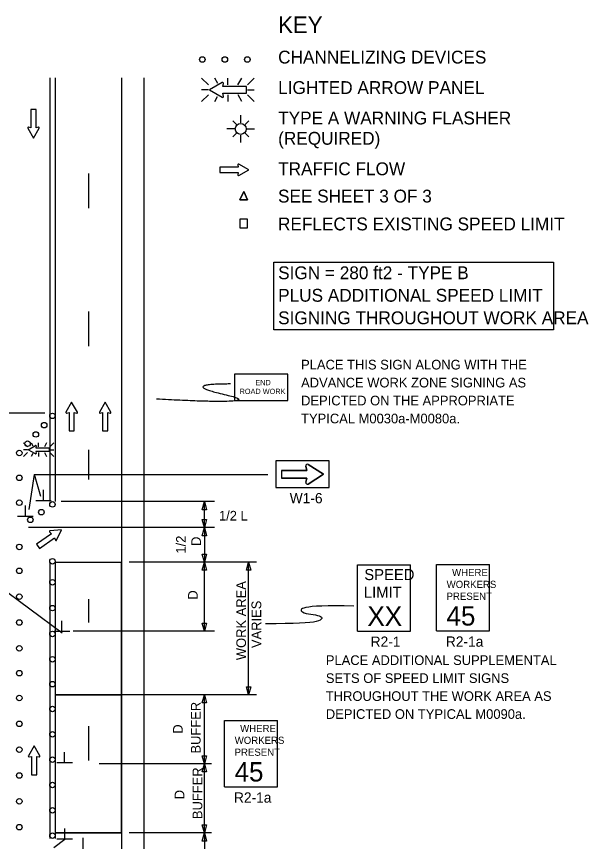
# Model space of a CAD drawing. Extents: x 16473 to 19504, y 4850 to 6923.
# Drawn here: x 17013 to 17427, y 6321 to 6918 of the extents above; entities that cross this region are included whole.
import ezdxf

# ---------------------------------------------------------------- set-up
doc = ezdxf.new("R2010")
doc.units = 0
for name, color, linetype in [('ALI_LEGAL_EX', 7, 'Continuous'), ('MT_SCRATCH_LEVEL_A', 7, 'Continuous'), ('MT_SCRATCH_LEVEL_E', 7, 'Continuous'), ('PAVT_EDGE_EX', 7, 'Continuous'), ('TRAFFIC_SIGNS_PR', 7, 'Continuous'), ('TYPICAL_TEXT_DIMEN_EX', 7, 'Continuous'), ('TYPICAL_TEXT_DIMEN_PR', 7, 'Continuous')]:
    doc.layers.add(name, color=color, linetype=linetype)

msp = doc.modelspace()

# ---------------------------------------------------------------- linework, layer by layer
at = {"layer": 'ALI_LEGAL_EX'}
for points in [[(17065.43, 6804.69), (17065.43, 6779.69)], [(17065.43, 6704.69), (17065.43, 6679.69)], [(17065.43, 6604.69), (17065.43, 6583.06)], [(17065.43, 6496.59), (17065.43, 6479.69)], [(17065.43, 6404.69), (17065.43, 6379.69)]]:
    msp.add_lwpolyline(points, dxfattribs=at)
at = {"layer": 'MT_SCRATCH_LEVEL_A'}
for p, q in [((17041.43, 6437.35), (17041.43, 6327.29)), ((17089.43, 6437.35), (17089.43, 6327.29)), ((17089.43, 6327.29), (17041.43, 6327.29))]:
    msp.add_line(p, q, dxfattribs=at)
for points in [[(17089.39, 6427.29), (17089.39, 6523.11), (17041.43, 6523.11), (17041.43, 6427.29)], [(17041.43, 6327.29), (17089.43, 6327.29), (17089.43, 6427.29), (17041.43, 6427.29)]]:
    msp.add_lwpolyline(points, close=True, dxfattribs=at)
at = {"layer": 'MT_SCRATCH_LEVEL_E'}
for p, q in [((17027.58, 6851.09), (17023.84, 6851.09)), ((17023.84, 6851.09), (17023.84, 6837.83)), ((17027.58, 6851.09), (17023.84, 6851.09)), ((17023.84, 6851.09), (17023.84, 6837.83)), ((17027.58, 6837.83), (17027.58, 6851.09)), ((17027.58, 6837.83), (17027.58, 6851.09)), ((17021.58, 6837.46), (17025.73, 6830.22)), ((17021.58, 6837.46), (17025.73, 6830.22)), ((17023.84, 6837.83), (17022.06, 6838.14)), ((17023.84, 6837.83), (17022.06, 6838.14)), ((17025.73, 6830.22), (17029.84, 6837.46)), ((17025.73, 6830.22), (17029.84, 6837.46)), ((17029.36, 6838.14), (17027.58, 6837.83)), ((17029.36, 6838.14), (17027.58, 6837.83)), ((17173.9, 6809.15), (17160.64, 6809.15)), ((17160.64, 6809.15), (17160.64, 6805.4)), ((17173.9, 6809.15), (17160.64, 6809.15)), ((17160.64, 6809.15), (17160.64, 6805.4)), ((17173.58, 6810.92), (17173.9, 6809.15)), ((17173.58, 6810.92), (17173.9, 6809.15)), ((17181.51, 6807.29), (17174.27, 6811.4)), ((17181.51, 6807.29), (17174.27, 6811.4)), ((17160.64, 6805.4), (17173.9, 6805.4)), ((17160.64, 6805.4), (17173.9, 6805.4)), ((17173.9, 6805.4), (17173.58, 6803.63)), ((17173.9, 6805.4), (17173.58, 6803.63)), ((17174.27, 6803.15), (17181.51, 6807.29)), ((17174.27, 6803.15), (17181.51, 6807.29)), ((17053.33, 6639.17), (17049.22, 6631.93)), ((17053.33, 6639.17), (17049.22, 6631.93)), ((17057.48, 6631.93), (17053.33, 6639.17)), ((17057.48, 6631.93), (17053.33, 6639.17)), ((17077.52, 6639.17), (17073.41, 6631.93)), ((17077.52, 6639.17), (17073.41, 6631.93)), ((17081.67, 6631.93), (17077.52, 6639.17)), ((17081.67, 6631.93), (17077.52, 6639.17)), ((17049.7, 6631.24), (17051.48, 6631.56)), ((17049.7, 6631.24), (17051.48, 6631.56)), ((17051.48, 6631.56), (17051.48, 6618.3)), ((17051.48, 6631.56), (17051.48, 6618.3)), ((17055.22, 6618.3), (17055.22, 6631.56)), ((17055.22, 6631.56), (17057, 6631.24)), ((17055.22, 6618.3), (17055.22, 6631.56)), ((17055.22, 6631.56), (17057, 6631.24)), ((17073.89, 6631.24), (17075.67, 6631.56)), ((17073.89, 6631.24), (17075.67, 6631.56)), ((17075.67, 6631.56), (17075.67, 6618.3)), ((17075.67, 6631.56), (17075.67, 6618.3)), ((17079.41, 6618.3), (17079.41, 6631.56)), ((17079.41, 6631.56), (17081.19, 6631.24)), ((17079.41, 6618.3), (17079.41, 6631.56)), ((17079.41, 6631.56), (17081.19, 6631.24)), ((17051.48, 6618.3), (17055.22, 6618.3)), ((17051.48, 6618.3), (17055.22, 6618.3)), ((17075.67, 6618.3), (17079.41, 6618.3)), ((17075.67, 6618.3), (17079.41, 6618.3)), ((17046, 6546.78), (17037.71, 6546)), ((17046, 6546.78), (17037.71, 6546)), ((17042.44, 6539.23), (17046, 6546.78)), ((17042.44, 6539.23), (17046, 6546.78)), ((17038.7, 6543.94), (17027.83, 6536.35)), ((17038.7, 6543.94), (17027.83, 6536.35)), ((17029.97, 6533.28), (17040.84, 6540.87)), ((17029.97, 6533.28), (17040.84, 6540.87)), ((17037.42, 6545.21), (17038.7, 6543.94)), ((17037.42, 6545.21), (17038.7, 6543.94)), ((17040.84, 6540.87), (17041.6, 6539.23)), ((17040.84, 6540.87), (17041.6, 6539.23)), ((17027.83, 6536.35), (17029.97, 6533.28)), ((17027.83, 6536.35), (17029.97, 6533.28)), ((17026.14, 6390.28), (17022.03, 6383.03)), ((17026.14, 6390.28), (17022.03, 6383.03)), ((17030.28, 6383.03), (17026.14, 6390.28)), ((17030.28, 6383.03), (17026.14, 6390.28)), ((17022.51, 6382.35), (17024.29, 6382.67)), ((17022.51, 6382.35), (17024.29, 6382.67)), ((17024.29, 6382.67), (17024.29, 6369.41)), ((17024.29, 6382.67), (17024.29, 6369.41)), ((17028.03, 6369.41), (17028.03, 6382.67)), ((17028.03, 6382.67), (17029.81, 6382.35)), ((17028.03, 6369.41), (17028.03, 6382.67)), ((17028.03, 6382.67), (17029.81, 6382.35)), ((17024.29, 6369.41), (17028.03, 6369.41)), ((17024.29, 6369.41), (17028.03, 6369.41))]:
    msp.add_line(p, q, dxfattribs=at)
for centre, start, end in [((17021.99, 6837.68), 80.03619, 209.77312), ((17021.99, 6837.68), 80.03619, 209.77312), ((17029.43, 6837.68), 330.42484, 99.96381), ((17029.43, 6837.68), 330.42484, 99.96381), ((17174.04, 6811), 60.42484, 189.96381), ((17174.04, 6811), 60.42484, 189.96381), ((17174.04, 6803.56), 170.03619, 299.77312), ((17174.04, 6803.56), 170.03619, 299.77312), ((17049.63, 6631.7), 150.42484, 279.96381), ((17049.63, 6631.7), 150.42484, 279.96381), ((17057.07, 6631.7), 260.03619, 29.77312), ((17057.07, 6631.7), 260.03619, 29.77312), ((17073.82, 6631.7), 150.42484, 279.96381), ((17073.82, 6631.7), 150.42484, 279.96381), ((17081.26, 6631.7), 260.03619, 29.77312), ((17081.26, 6631.7), 260.03619, 29.77312), ((17037.76, 6545.54), 95.35608, 224.89505), ((17037.76, 6545.54), 95.35608, 224.89505), ((17042.02, 6539.44), 204.96744, 334.70436), ((17042.02, 6539.44), 204.96744, 334.70436), ((17022.43, 6382.81), 150.42484, 279.96381), ((17022.43, 6382.81), 150.42484, 279.96381), ((17029.87, 6382.81), 260.03619, 29.77312), ((17029.87, 6382.81), 260.03619, 29.77312)]:
    msp.add_arc(centre, 0.463, start, end, dxfattribs=at)
at = {"layer": 'PAVT_EDGE_EX'}
for p, q in [((17037.43, 6873.99), (17037.43, 6567.11)), ((17041.43, 6873.99), (17041.43, 6567.11)), ((17089.43, 6873.99), (17089.43, 6149.2)), ((17105.43, 6873.99), (17105.43, 6149.2)), ((17037.43, 6523.35), (17037.43, 6323.29)), ((17041.43, 6523.35), (17041.43, 6476.48)), ((17041.43, 6437.35), (17041.43, 6323.29))]:
    msp.add_line(p, q, dxfattribs=at)
at = {"layer": 'TRAFFIC_SIGNS_PR'}
for p, q in [((17147.32, 6873.68), (17152.25, 6868.75)), ((17159.08, 6869.86), (17156.87, 6873.68)), ((17166.4, 6868.75), (17166.4, 6873.68)), ((17173.64, 6868.75), (17176.48, 6873.68)), ((17180.55, 6868.75), (17185.49, 6873.68)), ((17152.25, 6865.19), (17147.32, 6865.19)), ((17180.55, 6865.19), (17185.49, 6865.19)), ((17147.32, 6856.7), (17152.25, 6861.63)), ((17156.83, 6856.7), (17158.94, 6860.36)), ((17166.4, 6861.63), (17166.4, 6856.7)), ((17176.53, 6856.7), (17173.68, 6861.63)), ((17180.55, 6861.63), (17185.49, 6856.7)), ((17175.66, 6841.4), (17175.66, 6847.02)), ((17172.52, 6840.1), (17169.89, 6842.73)), ((17178.79, 6840.1), (17181.43, 6842.73)), ((17171.72, 6836.96), (17165.68, 6836.96)), ((17172.52, 6833.82), (17169.89, 6831.19)), ((17175.66, 6827.01), (17175.66, 6832.52)), ((17178.79, 6833.82), (17181.42, 6831.19)), ((17179.59, 6836.96), (17185.69, 6836.96)), ((17018.55, 6609.58), (17021.37, 6606.76)), ((17023.98, 6609.58), (17025.19, 6607.49)), ((17029.45, 6606.76), (17029.45, 6609.58)), ((17035.24, 6609.58), (17033.61, 6606.76)), ((17037.54, 6606.76), (17040.36, 6609.58)), ((17021.37, 6604.73), (17018.55, 6604.73)), ((17018.55, 6599.88), (17021.37, 6602.7)), ((17025.27, 6602.06), (17024.01, 6599.88)), ((17029.45, 6602.7), (17029.45, 6599.88)), ((17033.59, 6602.7), (17035.21, 6599.88)), ((17037.54, 6604.73), (17040.36, 6604.73)), ((17037.54, 6602.7), (17040.36, 6599.88)), ((17224.39, 6594.08), (17235.55, 6586.98)), ((17205.15, 6589.78), (17223.55, 6589.78)), ((17205.15, 6589.78), (17205.15, 6584.18)), ((17223.55, 6589.78), (17222.71, 6592.84)), ((17223.55, 6584.18), (17205.15, 6584.18)), ((17222.71, 6581.12), (17223.55, 6584.18)), ((17235.55, 6586.98), (17224.39, 6579.88)), ((17260.04, 6521.47), (17298.44, 6521.47)), ((17260.04, 6473.47), (17260.04, 6521.47)), ((17298.44, 6473.47), (17298.44, 6521.47)), ((17317.23, 6521.55), (17355.63, 6521.55)), ((17317.23, 6473.55), (17317.23, 6521.55)), ((17355.63, 6473.55), (17355.63, 6521.55)), ((17260.04, 6473.47), (17298.44, 6473.47)), ((17317.23, 6473.55), (17355.63, 6473.55)), ((17163.91, 6408.66), (17202.31, 6408.66)), ((17163.91, 6360.66), (17163.91, 6408.66)), ((17202.31, 6360.66), (17202.31, 6408.66)), ((17163.91, 6360.66), (17202.31, 6360.66))]:
    msp.add_line(p, q, dxfattribs=at)
for points in [[(17162.33, 6870.47), (17153.04, 6865.19), (17162.33, 6859.87)], [(17163.2, 6860.5), (17162.8, 6862.76), (17179.82, 6862.76), (17179.82, 6867.57), (17162.8, 6867.57), (17163.21, 6869.85)], [(17177.79, 6791.69), (17175, 6785.52)], [(17175, 6785.52), (17177.79, 6791.69)], [(17180.59, 6785.52), (17177.79, 6791.69)], [(17177.79, 6791.69), (17180.59, 6785.52)], [(17175, 6785.52), (17180.59, 6785.52)], [(17180.59, 6785.52), (17175, 6785.52)], [(17027.12, 6601.72), (17021.81, 6604.73), (17027.12, 6607.77)], [(17027.62, 6607.41), (17027.4, 6606.12), (17037.12, 6606.12), (17037.12, 6603.37), (17027.4, 6603.37), (17027.63, 6602.07)], [(17224.39, 6579.88), (17235.55, 6586.98), (17224.39, 6594.08)], [(17222.71, 6592.84), (17223.55, 6589.78), (17205.15, 6589.78), (17205.15, 6584.18), (17223.55, 6584.18), (17222.71, 6581.12)]]:
    msp.add_lwpolyline(points, dxfattribs=at)
for points in [[(17175, 6765.34), (17180.59, 6765.34), (17180.59, 6771.51), (17175, 6771.51)], [(17171.21, 6640.28), (17209.61, 6640.28), (17209.61, 6659.48), (17171.21, 6659.48)], [(17201.15, 6577.38), (17239.55, 6577.38), (17239.55, 6596.58), (17201.15, 6596.58)]]:
    msp.add_lwpolyline(points, close=True, dxfattribs=at)
for centre, radius in [((17147.88, 6887.22), 2), ((17164.18, 6887.22), 2), ((17180.48, 6887.22), 2), ((17175.66, 6836.96), 3.94), ((17039.43, 6629.2), 2), ((17033.43, 6622.48), 2), ((17027.43, 6615.77), 2), ((17021.43, 6609.06), 2), ((17015.43, 6602.35), 2), ((17015.43, 6584.35), 2), ((17015.43, 6566.35), 2), ((17039.43, 6565.11), 2), ((17031.43, 6559.53), 2), ((17023.43, 6553.94), 2), ((17015.43, 6534.35), 2), ((17039.43, 6523.95), 2), ((17015.43, 6517.05), 2), ((17039.43, 6508.75), 2), ((17015.43, 6498.35), 2), ((17039.43, 6490.05), 2), ((17015.43, 6479.66), 2), ((17039.43, 6471.35), 2), ((17015.43, 6460.96), 2), ((17039.43, 6453.01), 2), ((17015.43, 6442.96), 2), ((17039.43, 6435.01), 2), ((17015.43, 6424.96), 2), ((17039.43, 6417.01), 2), ((17015.43, 6406.26), 2), ((17039.43, 6398.66), 2), ((17015.43, 6387.57), 2), ((17039.43, 6380.32), 2), ((17015.43, 6368.87), 2), ((17039.43, 6361.98), 2), ((17015.43, 6350.17), 2), ((17039.43, 6343.63), 2), ((17015.43, 6331.47), 2), ((17039.43, 6325.29), 2)]:
    msp.add_circle(centre, radius, dxfattribs=at)
for centre, radius, start, end in [((17162.62, 6869.94), 0.598, 350.73078, 118.89165), ((17162.61, 6860.39), 0.597, 241.48329, 9.95933), ((17027.29, 6607.47), 0.341, 350.04067, 118.51671), ((17027.29, 6602.02), 0.341, 241.10835, 9.26922), ((17223.79, 6593.14), 1.12, 57.53038, 195.32692), ((17223.79, 6593.14), 1.12, 57.53038, 195.32692), ((17223.79, 6580.82), 1.12, 164.67308, 302.46962), ((17223.79, 6580.82), 1.12, 164.67308, 302.46963)]:
    msp.add_arc(centre, radius, start, end, dxfattribs=at)
msp.add_open_spline([(17168.26, 6652.3), (17130.47, 6652.3), (17198.49, 6636.82), (17114.68, 6641.31)], degree=2, dxfattribs=at)
at = {"layer": 'TYPICAL_TEXT_DIMEN_EX'}
msp.add_lwpolyline([(17199.71, 6740.56), (17402.04, 6740.56), (17402.04, 6691.5), (17199.71, 6691.5)], close=True, dxfattribs=at)
at = {"layer": 'TYPICAL_TEXT_DIMEN_PR'}
for p, q in [((17034.03, 6631.18), (16924.43, 6631.18)), ((17026.15, 6586.76), (17022.28, 6561.48)), ((17026.16, 6586.76), (17195.27, 6586.76)), ((17031.07, 6570.81), (17026.34, 6586.81)), ((17032.96, 6567.81), (17032.96, 6575.6)), ((17019.85, 6556.45), (17019.85, 6564.23)), ((17038.59, 6567.81), (17027.34, 6567.81)), ((17156.64, 6567.11), (17045.85, 6567.11)), ((17147.86, 6561.25), (17149.43, 6567.11)), ((17149.43, 6548.35), (17149.43, 6567.11)), ((17149.43, 6567.11), (17151, 6561.25)), ((17149.43, 6561.25), (17147.86, 6561.25)), ((17151, 6561.25), (17149.43, 6561.25)), ((17025.47, 6556.45), (17014.22, 6556.45)), ((17149.43, 6548.35), (17147.86, 6554.22)), ((17147.86, 6554.22), (17149.43, 6554.22)), ((17149.43, 6554.22), (17151, 6554.22)), ((17151, 6554.22), (17149.43, 6548.35)), ((17156.64, 6548.35), (17022.11, 6548.35)), ((17147.86, 6542.49), (17149.43, 6548.35)), ((17149.43, 6548.35), (17151, 6542.49)), ((17149.43, 6548.35), (17149.43, 6523.35)), ((16950.55, 6543.14), (17046.41, 6472.14)), ((17149.43, 6542.49), (17147.86, 6542.49)), ((17151, 6542.49), (17149.43, 6542.49)), ((17149.43, 6523.35), (17147.86, 6529.22)), ((17147.86, 6529.22), (17149.43, 6529.22)), ((17149.43, 6529.22), (17151, 6529.22)), ((17151, 6529.22), (17149.43, 6523.35)), ((17186.99, 6523.35), (17094.94, 6523.35)), ((17168.56, 6523.35), (17094.94, 6523.35)), ((17147.86, 6517.49), (17149.43, 6523.35)), ((17149.43, 6473.35), (17149.43, 6523.35)), ((17149.43, 6523.35), (17151, 6517.49)), ((17179.77, 6517.49), (17181.34, 6523.35)), ((17181.34, 6427.29), (17181.34, 6523.35)), ((17181.34, 6523.35), (17182.91, 6517.49)), ((17149.43, 6517.49), (17147.86, 6517.49)), ((17151, 6517.49), (17149.43, 6517.49)), ((17181.34, 6517.49), (17179.77, 6517.49)), ((17182.91, 6517.49), (17181.34, 6517.49)), ((17046.3, 6473.15), (17046.3, 6480.93)), ((17149.43, 6473.35), (17147.86, 6479.22)), ((17147.86, 6479.22), (17149.43, 6479.22)), ((17149.43, 6479.22), (17151, 6479.22)), ((17151, 6479.22), (17149.43, 6473.35)), ((17051.92, 6473.15), (17040.67, 6473.15)), ((17156.64, 6473.35), (17054.5, 6473.35)), ((17181.34, 6427.29), (17179.77, 6433.15)), ((17179.77, 6433.15), (17181.34, 6433.15)), ((17181.34, 6433.15), (17182.91, 6433.15)), ((17182.91, 6433.15), (17181.34, 6427.29)), ((17186.99, 6427.29), (17089.43, 6427.29)), ((17147.86, 6421.43), (17149.43, 6427.29)), ((17149.43, 6377.29), (17149.43, 6427.29)), ((17149.43, 6427.29), (17151, 6421.43)), ((17149.43, 6421.43), (17147.86, 6421.43)), ((17151, 6421.43), (17149.43, 6421.43)), ((17048.2, 6377.98), (17048.2, 6385.77)), ((17149.43, 6377.29), (17147.86, 6383.15)), ((17147.86, 6383.15), (17149.43, 6383.15)), ((17149.43, 6383.15), (17151, 6383.15)), ((17151, 6383.15), (17149.43, 6377.29)), ((17053.83, 6377.98), (17042.58, 6377.98)), ((17154.43, 6377.29), (17073.2, 6377.29)), ((17147.86, 6371.43), (17149.43, 6377.29)), ((17149.43, 6327.29), (17149.43, 6377.29)), ((17149.43, 6377.29), (17151, 6371.43)), ((17149.43, 6371.43), (17147.86, 6371.43)), ((17151, 6371.43), (17149.43, 6371.43)), ((17149.43, 6327.29), (17147.86, 6333.15)), ((17147.86, 6333.15), (17149.43, 6333.15)), ((17149.43, 6333.15), (17151, 6333.15)), ((17151, 6333.15), (17149.43, 6327.29)), ((17048.33, 6322.74), (17048.33, 6330.52)), ((17154.43, 6327.29), (17094.94, 6327.29)), ((17147.86, 6321.43), (17149.43, 6327.29)), ((17149.43, 6327.29), (17149.43, 6305.72)), ((17149.43, 6327.29), (17151, 6321.43)), ((17040.39, 6316.77), (17048.33, 6322.74)), ((17053.96, 6322.74), (17042.71, 6322.74)), ((17061.59, 6315.87), (17061.59, 6323.65)), ((17149.43, 6321.43), (17147.86, 6321.43)), ((17151, 6321.43), (17149.43, 6321.43))]:
    msp.add_line(p, q, dxfattribs=at)
msp.add_open_spline([(17257.51, 6491.44), (17217.42, 6492.7), (17217.42, 6485.46), (17235.31, 6485.46), (17235.31, 6479.61), (17215.36, 6478.82), (17193.67, 6478.61)], degree=3, dxfattribs=at)

# ---------------------------------------------------------------- texts
at = {"layer": 'TRAFFIC_SIGNS_PR'}
for s, height, p in [('PLACE THIS SIGN ALONG WITH THE', 7, (17219.32, 6662.8)), ('END', 3.831, (17186.21, 6651.4)), ('ADVANCE WORK ZONE SIGNING AS', 7, (17219.32, 6649.8)), ('ROAD WORK', 3.831, (17174.82, 6645.02)), ('DEPICTED ON THE APPROPRIATE', 7, (17219.32, 6636.8)), ('TYPICAL M0030a-M0080a.', 7, (17219.32, 6623.8)), ('W1-6', 7.44, (17211.09, 6565.94)), ('SPEED', 8, (17265.07, 6510.33)), ('WHERE', 5.2, (17328.54, 6513.24)), ('WORKERS', 5.2, (17324.62, 6504.64)), ('LIMIT', 8, (17264.74, 6497.53)), ('PRESENT', 5.2, (17324.55, 6496.04)), ('XX', 14.031, (17267.34, 6477.22)), ('45', 14.031, (17324.54, 6477.41)), ('R2-1', 7.44, (17269.65, 6462.03)), ('R2-1a', 7.44, (17324.09, 6462.11)), ('PLACE ADDITIONAL SUPPLEMENTAL', 7, (17237.23, 6448.86)), ('SETS OF SPEED LIMIT SIGNS', 7, (17237.23, 6435.86)), ('THROUGHOUT THE WORK AREA AS', 7, (17237.23, 6422.86)), ('DEPICTED ON TYPICAL M0090a.', 7, (17237.23, 6409.86)), ('WHERE', 5.2, (17175.22, 6400.35)), ('WORKERS', 5.2, (17171.3, 6391.75)), ('PRESENT', 5.2, (17171.23, 6383.15)), ('45', 14.031, (17171.22, 6364.52)), ('R2-1a', 7.44, (17170.77, 6349.22))]:
    msp.add_text(s, height=height, dxfattribs=at).set_placement(p)
at = {"layer": 'TYPICAL_TEXT_DIMEN_EX'}
for s, height, p in [('KEY', 12, (17202.72, 6906.33)), ('CHANNELIZING DEVICES', 9.3, (17202.72, 6884.28)), ('LIGHTED ARROW PANEL', 9.3, (17202.72, 6862.23)), ('TYPE A WARNING FLASHER', 9.3, (17202.72, 6840.18)), ('(REQUIRED)', 9.3, (17202.72, 6825.48)), ('TRAFFIC FLOW', 9.3, (17202.72, 6803.43)), ('SEE SHEET 3 OF 3', 9.3, (17202.63, 6783.68)), ('REFLECTS EXISTING SPEED LIMIT', 9.3, (17202.63, 6763.5)), ('SIGN = 280 ft2 - TYPE B', 9.3, (17202.72, 6728.15)), ('PLUS ADDITIONAL SPEED LIMIT', 9.3, (17202.72, 6711.85)), ('SIGNING THROUGHOUT WORK AREA', 9.3, (17202.72, 6695.55))]:
    msp.add_text(s, height=height, dxfattribs=at).set_placement(p)
at = {"layer": 'TYPICAL_TEXT_DIMEN_PR'}
msp.add_text('1/2 L', height=7, dxfattribs=at).set_placement((17159.9, 6553.44))
for s, p in [('1/2', (17135.87, 6529.5)), ('D', (17146.87, 6535.07)), ('WORK AREA', (17179.46, 6452.39)), ('D', (17144.5, 6496.19)), ('VARIES', (17190.46, 6461.11)), ('BUFFER', (17146.64, 6384.76)), ('D', (17133.64, 6399.12)), ('BUFFER', (17147.83, 6337.31)), ('D', (17134.83, 6351.67))]:
    msp.add_text(s, height=7, rotation=90, dxfattribs=at).set_placement(p)

doc.saveas('drawing.dxf')
